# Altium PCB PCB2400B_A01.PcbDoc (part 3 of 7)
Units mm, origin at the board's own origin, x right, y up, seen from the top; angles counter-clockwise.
Board outline 115 x 60 mm, 6 copper layers (Top Layer, Signal Layer 2, Signal Layer 3, Signal Layer 4, Signal Layer 5, Bottom Layer), stack 1.555 mm thick; 382 components, 308 nets, 1384 pads, 1152 vias.
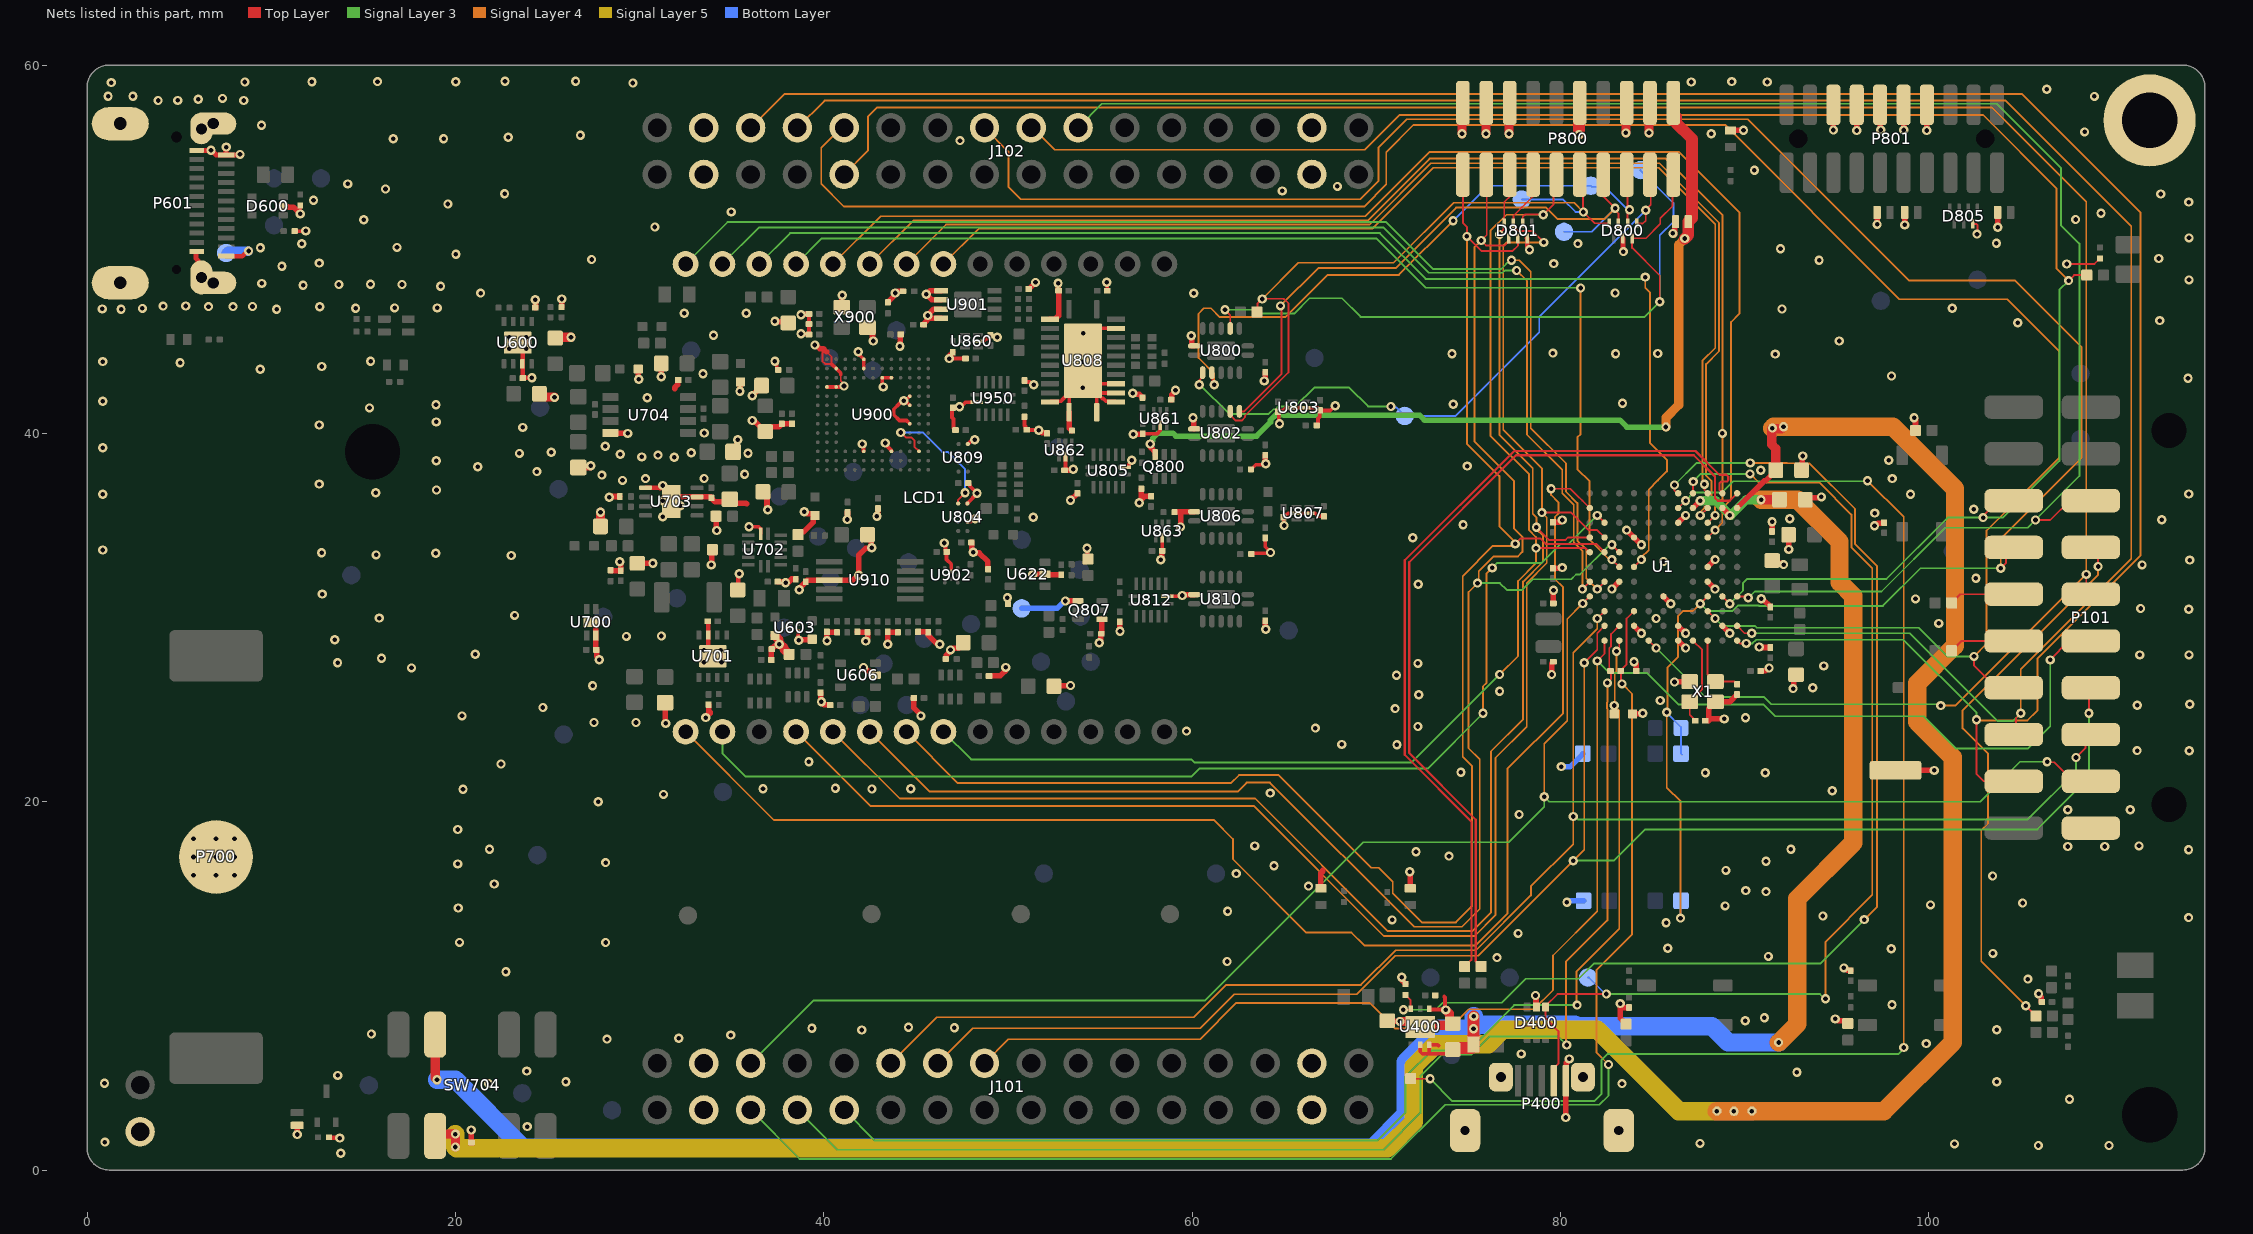
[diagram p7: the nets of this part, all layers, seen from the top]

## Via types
v1: diameter 0.5, hole 0.25, Top Layer to Bottom Layer, tented both sides, 773 vias
v2: diameter 0.508, hole 0.25, Top Layer to Bottom Layer, tented both sides, 379 vias

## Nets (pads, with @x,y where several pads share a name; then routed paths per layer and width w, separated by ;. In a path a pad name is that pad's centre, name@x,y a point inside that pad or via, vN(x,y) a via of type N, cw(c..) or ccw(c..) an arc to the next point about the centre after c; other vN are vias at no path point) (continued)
DEBUG_TMS_SWDIO_OUT: U804.D2 U900.C2 | length 7.8
  Top Layer w0.1: v2@44.275,39.975 44.275,39.972 44.472,39.775 44.779,39.775 44.925,39.629 44.925,39.275 U900.C2@45.175,39.025 ; U804.D2@47.3,36.2 47.3,36.4 v2(47.674,36.774)
  Bottom Layer w0.1: v2(44.177,40.052) 45.373,40.052 46.425,39 46.725,39 47.674,38.051 v2(47.674,36.774)
DEBUG_TRACECLK: D801.2 LCD1.8 P800.12 U1.E1 | length 68.9
  Top Layer w0.1: D801.2@77.95,51.415 77.955,51.42 77.955,51.771 78.084,51.9 79.1,51.9 79.621,52.421 79.621,53.813 P800.12@79.746,53.938 ; v1(78.675,33.775) 81.375,33.775 U1.E1@81.6,33.55
  Signal Layer 3 w0.1: LCD1.8@46.5,23.8 48,22.3 59.958,22.3 60.122,22.136 71.925,22.136 v1(76.7,26.911)
  Signal Layer 4 w0.1: v1(76.7,26.911) 77.7,27.911 77.7,31.983 78.675,32.958 v1(78.675,33.775) 78.675,34.375 78.3,34.75 78.3,37.775 76.2,39.875 76.2,51 77.075,51.875 v1(79.075,51.875)
DEBUG_TRACED0: D801.3 LCD1.4 P800.14 U1.D2 | length 92.7
  Top Layer w0.1: D801.3@77.45,51.415 77.45,51.807 78.515,52.872 P800.14@78.515,53.968 ; D801.3@77.475,51.22 77.695,51 78.475,51 v1(79.1,50.375) ; v1(79,35.7) 80.587,35.7 81.537,34.75 82,34.75 U1.D2@82.4,34.35
  Signal Layer 4 w0.1: LCD1.4@38.5,23.8 42.525,19.775 63.349,19.775 70.423,12.702 75.338,12.702 76.475,13.839 76.475,22.375 78.175,24.075 78.175,31.875 79.264,32.964 79.264,35.436 v1(79,35.7) 79,38.1 76.9,40.2 76.9,50.2 77.075,50.375 v1(79.1,50.375)
DEBUG_TRACED1: D801.4 LCD1.5 P800.16 U1.D1 | length 85.9
  Top Layer w0.1: v1@76.625,50.8 76.914,51.089 76.914,51.379 D801.4@76.95,51.415 76.95,52.567 77.325,52.942 P800.16@77.325,53.525 ; v1(78.7,34.9) 79.389,34.211 80.268,34.211 80.407,34.35 U1.D1@81.6,34.35
  Signal Layer 4 w0.1: LCD1.5@40.5,23.8 44.125,20.175 63.425,20.175 70.627,12.973 75.223,12.973 76.228,13.978 76.228,22.728 77.975,24.475 77.975,31.958 79.064,33.047 79.064,34.439 78.7,34.803 78.7,35.45 78.5,35.65 78.5,38.1 76.7,39.9 v1(76.7,50.8)
DEBUG_TRACED2: D801.5 LCD1.6 P800.18 U1.E3 | length 92.5
  Top Layer w0.1: P800.18@75.975,53.968 76,53.943 76,50.775 v1(75.7,50.475) 75.969,50.206 76.981,50.206 77.145,50.37 77.155,50.37 77.23,50.445 D801.5@77.23,50.455 ; v1(82.8,33.95) U1.E3@83.2,33.55
  Signal Layer 3 w0.1: v1(75.5,31.875) 76.715,31.875 77.09,31.5 77.925,31.5 78.503,32.078 80.589,32.078 80.85,32.339 81.064,32.339 82.675,33.95 v1(82.8,33.95)
  Signal Layer 4 w0.1: LCD1.6@42.5,23.8 45.75,20.55 62.475,20.55 62.964,21.039 64.227,21.039 72.057,13.209 74.659,13.209 75.625,14.175 75.625,22.295 75.011,22.909 75.011,31.386 v1(75.5,31.875) 75.569,31.944 75.569,32.519 76.375,33.325 77.7,33.325 77.939,33.564 77.939,34.378 77.489,34.828 77.489,37.411 75.336,39.564 75.336,50.111 v1(75.7,50.475)
DEBUG_TRACED3: D801.6 LCD1.7 P800.20 U1.E2 | length 87.8
  Top Layer w0.1: P800.20@74.705,53.968 74.705,51.445 74.925,51.225 v1(74.925,50.7) 75.725,49.9 77.4,49.9 77.7,50.2 D801.6@77.7,50.585 ; v1(77.55,34) 77.85,34.3 78.9,34.3 79.2,34 81.95,34 U1.E2@82.4,33.55
  Signal Layer 4 w0.1: LCD1.7@44.5,23.8 47.289,21.011 62.111,21.011 62.55,21.45 64.7,21.45 69.738,16.412 70.137,16.412 70.9,15.65 70.9,15.025 72.475,13.45 74.325,13.45 75.2,14.325 75.2,21.95 74.7,22.45 74.7,32.25 76.34,33.89 77.44,33.89 v1(77.55,34) 77.55,34.097 76.689,34.958 76.689,37.686 74.925,39.45 v1(74.925,50.7)
DH_#RESET: D800.4 P800.10 R816.1 TPJ811.1 U802.3 | length 37.9
  Top Layer w0.1: U802.3@62.075,41.2 62.075,41 62.375,40.7 62.699,40.7 62.875,40.876 62.875,40.95 65.239,43.314 65.239,47.061 65,47.3 64.975,47.3 64.962,47.313 63.82,47.313 v1(63.807,47.3) ; R816.1@63.525,46.6 63.55,46.625 63.55,47.05 v1@63.8,47.3 ; P800.10@81.016,53.988 81.222,53.782 81.222,52.053 v1(81.25,52.025) 81.86,51.415 D800.4@82.65,51.415
  Signal Layer 4 w0.1: v1(63.807,47.3) 65.773,49.266 70.941,49.266 74.2,52.525 80.75,52.525 v1(81.25,52.025)
  Bottom Layer w0.1: TPJ811.1@77.92,52.7 80.15,52.7 80.825,52.025 v1(81.25,52.025)
DH_TCK_SWCLK: D800.1 P800.4 TPJ818.1 U800.9 | length 35
  Top Layer w0.1: v2(60.4,42.65) 60.4,42.9 60.575,43.075 U800.9@60.575,43.3 ; D800.1@84.195,51.4 84.475,51.4 84.636,51.561 84.636,52.144 84.906,52.414 84.906,53.932 P800.4@84.87,53.968
  Signal Layer 3 w0.1: v2(60.4,42.65) 60.431,42.65 62.022,41.059 64.168,41.059 64.423,41.314 64.54,41.314 64.69,41.464 65.614,41.464 66.639,42.489 68.536,42.489 69.561,41.464 v1(70.8,41.464)
  Bottom Layer w0.1: v1(70.8,41.464) 70.854,41.41 71.09,41.41 TPJ818.1@71.55,40.95 72.45,40.95 74.313,40.95 78.858,45.495 78.858,46.341 v1(84.636,52.119)
DH_TDI: D800.3 P800.8 TPJ820.1 U802.2 | length 33.9
  Top Layer w0.1: U802.2@62.575,41.2 62.831,41.2 64.85,43.219 64.85,46.9 64.825,46.9 v1(64.801,46.924) ; P800.8@82.325,53.968 82.325,52.875 v1(82.975,52.225) 82.975,52.117 83.15,51.942 D800.3@83.15,51.415
  Signal Layer 4 w0.1: v1(64.801,46.924) 66.855,48.978 71.053,48.978 74.339,52.264 79.236,52.264 79.864,51.636 82.386,51.636 v1(82.975,52.225)
  Bottom Layer w0.1: TPJ820.1@80.2,50.95 81.7,50.95 v1(82.975,52.225)
DH_TDO_SWO: D800.2 P800.6 TPJ812.1 U800.10 | length 35
  Top Layer w0.1: v2@61.075,42.725 61.122,42.772 61.122,42.838 61.113,42.847 61.113,43.262 U800.10@61.075,43.3 ; P800.6@83.556,53.988 83.65,53.894 v1@83.65,52.15 ; D800.2@83.65,51.275 v1@83.65,52.15 ; v1(83.753,52.15) v1@83.65,52.15
  Signal Layer 4 w0.1: v2(61.2,42.65) 61.2,43.25 60.35,44.1 60.35,46.5 60.646,46.796 61.029,46.796 61.504,46.321 65.071,46.321 67.359,48.609 71.234,48.609 v1(74.175,51.55)
  Bottom Layer w0.1: v1@74.062,51.437 v1(74.175,51.55) 76.075,53.45 TPJ812.1@81.65,53.45 81.708,53.392 82.408,53.392 83.65,52.15 v1(83.753,52.15)
DH_TMS_SWDIO: D800.7 P800.2 TPJ814.1 U800.3 | length 42.9
  Top Layer w0.1: v2(61.789,46.714) 62.075,46.427 U800.3@62.075,45.7 ; v1(85.4,47.15) 85.4,48.575 83.9,50.075 83.9,50.555 83.945,50.6 84.65,50.6 85.425,51.375 85.425,51.68 86.096,52.351 P800.2@86.096,53.988
  Signal Layer 3 w0.1: v2(61.789,46.714) 63.625,46.714 63.827,46.511 65.553,46.511 66.379,47.337 68.142,47.337 69.152,46.327 84.577,46.327 v1(85.4,47.15)
  Bottom Layer w0.1: TPJ814.1@84.35,54.3 86.144,52.506 86.144,51.495 85.4,50.751 v1(85.4,47.15)
DH_VTREF: D809.1 P800.1 Q800.3 | length 47.7
  Top Layer w0.3: v2(57.725,39.425) 57.765,39.385 57.765,39.235 58,39 Q800.3@58,38.85
  Top Layer w0.635: P800.1@86.275,57.2 86.275,56.868 87.15,55.993 87.15,51.7 D809.1@86.983,51.533 ; v1(86.761,50.583) 86.95,50.772 D809.1@86.95,51.5
  Signal Layer 3 w0.3: v2(57.725,39.425) 57.725,39.481 57.857,39.613 57.857,39.729 58.146,40.018 58.96,40.018 59.121,39.857 63.507,39.857 64.261,40.611 64.261,40.728 64.547,41.014 64.953,41.014 64.991,40.975 72.373,40.975 72.623,40.725 83.238,40.725 83.616,40.347 v1(85.734,40.347)
  Signal Layer 4 w0.5: v1(85.734,40.347) 85.734,40.859 86.425,41.55 86.425,50.247 v1(86.761,50.583)
EFM_USB_DM: R406.2 U1.A10 | length 45.7
  Top Layer w0.12: R406.2@74.8,11.05 75.168,11.418 75.168,18.927 71.55,22.545 71.55,33.108 77.493,39.051 87.343,39.051 88.636,37.758 89.007,37.758 89.118,37.647 89.118,37.465 89.048,37.395 88.75,37.395 88.636,37.281 88.636,36.935 88.8,36.771 U1.A10@88.8,36.75
EFM_USB_DP: R405.2 U1.A11 | length 45.7
  Top Layer w0.12: R405.2@75.7,11.05 75.408,11.342 75.408,19.026 71.79,22.644 71.79,33.009 77.592,38.811 87.243,38.811 88.394,37.661 88.394,36.499 88.545,36.348 89.198,36.348 U1.A11@89.6,36.75
EFM_USB_ID: D400.1 P400.4 TPJ402.1 U1.A8 | length 59.5
  Top Layer w0.1: P400.4@79.65,4.85 79.65,5.525 79.897,5.771 79.897,7.548 79.2,8.245 79.2,8.912 79.847,9.56 v1(82.503,9.56) ; U1.A8@87.2,36.75 87.213,36.763 v1(87.213,37.386)
  Signal Layer 3 w0.1: v1(82.503,9.56) 94.094,9.56 v1@94.354,9.3 ; v1(87.213,37.386) 87.627,37.8 v1(90.3,37.8)
  Signal Layer 4 w0.1: v1(90.3,37.8) 90.759,37.341 94.059,37.341 95.807,35.593 95.807,33.82 96.939,32.688 96.939,14.939 94.4,12.4 v1(94.4,9.3)
  Bottom Layer w0.1: TPJ402.1@81.5,10.45 81.556,10.45 82.447,9.56 v1(82.503,9.56)
EFM_USB_OC_FAULT: R408.1 U1.B7 | length 72.1
  Top Layer w0.1: U1.B7@86.401,35.95 v1(86.801,36.35)
  Top Layer w0.102: R408.1@71.874,4.968 71.883,4.959 v1(72.927,4.959)
  Signal Layer 3 w0.102: v1(72.927,4.959) 74.141,3.745 81.842,3.745 82.226,4.128 82.226,5.966 82.56,6.3 98.36,6.3 98.647,6.587 v1(98.647,6.654) ; v1(86.801,36.35) 87.251,36.8 88.8,36.8 89.4,37.4 96.645,37.4 v1(96.677,37.432)
  Signal Layer 4 w0.102: v1(96.677,37.432) 98.647,35.463 v1(98.647,6.654)
EFM_USB_VBUS: C402.1 C420.1 L401.2 SW704.6 U1.B8 U1.B10 U400.5 U400.6 | length 128.4
  Top Layer w0.2: U400.5@72.387,6.801 72.387,6.426 72.504,6.309 72.765,6.309 ; 73.382,6.757 73.338,6.801 U400.6@72.887,6.801 72.882,6.796 72.882,6.426 72.765,6.309 ; C420.1@74.151,6.545 73.915,6.309 72.765,6.309
  Top Layer w0.3: U1.B8@87.201,35.95 v1(87.601,36.35) ; U1.B10@88.8,35.95 v1(89.201,35.55)
  Top Layer w0.5: SW704.6@18.9,7.25 18.9,5 v1(19,4.9) ; v1(90.9,36.4) C402.1@91.8,36.4
  Top Layer w0.635: C420.1@74.151,6.545 C420.1@74.176,6.545 ; C420.1@74.233,6.628 L401.2@75.198,6.628 ; L401.2@75.286,6.716 75.286,7.666 v1(75.283,7.669) 75.283,8.33 v1(75.297,8.344)
  Signal Layer 3 w0.5: v1(87.601,36.35) 88.439,36.35 89.201,35.588 v1(89.201,35.55) 89.25,35.55 90.1,36.4 v1(90.9,36.4)
  Signal Layer 4 w1: v1(90.9,36.4) 92.885,36.4 95.157,34.128 95.157,31.927 95.904,31.18 95.904,17.775 92.871,14.742 92.871,7.93 91.868,6.927 v1(91.853,6.927)
  Bottom Layer w1: v1(19,4.9) 20,4.9 23.7,1.2 69.8,1.2 71.6,3 71.6,5.864 73.405,7.669 v1(75.283,7.669) 75.283,8.33 v1(75.297,8.344) ; 75.5,7.886 80.794,7.886 80.868,7.812 88.234,7.812 89.118,6.927 v1(91.853,6.927)
EFM_USB_VBUSEN: R407.2 U1.A7 U400.3 | length 63.4
  Top Layer w0.1: v1(71.478,8.703) 71.839,8.703 U400.3@71.887,8.751 71.871,8.767 71.871,9.226 71.714,9.383 71.704,9.383 71.594,9.493 R407.2@71.594,9.503 ; v1(86.2,37.2) 86.2,36.884 86.334,36.75 U1.A7@86.4,36.75 U1.A7@86.425,36.75 ; v1@86.2,37.225 v1@86.212,37.213
  Signal Layer 3 w0.1: v1(71.478,8.703) 71.481,8.7 73.238,8.7 ; 73.24,8.702 73.622,9.085 76.808,9.085 78.109,10.386 80.986,10.386 81.813,11.213 ; 81.811,11.211 94.111,11.211 v1(96.5,13.6) ; v1(86.2,37.2) 87.4,38.4 v1(90.315,38.4)
  Signal Layer 4 w0.1: v1(90.315,38.4) 90.321,38.394 92.302,38.394 92.311,38.385 93.519,38.385 96.007,35.897 96.007,33.98 97.2,32.787 97.2,14.3 v1(96.5,13.6)
EFM_USB_VREGO: C401.1 SW704.2 U1.B11 | length 142.7
  Top Layer w0.3: U1.B11@89.6,35.95 91.071,37.422 91.146,37.422 91.7,37.975 C401.1@91.7,38
  Top Layer w0.5: SW704.2@18.9,1.95 v1(20,1.95) v1(20,1.25) ; v1(91.516,40.288) v1@91.478,40.249 ; C401.1@91.7,38 91.7,39.175 91.478,39.397 v1@91.478,40.249 ; v1(92.115,40.364) 92,40.249 v1@91.478,40.249
  Signal Layer 4 w1: v1(88.5,3.2) 88.505,3.195 v1(89.424,3.195) 89.428,3.2 v1(90.4,3.2) 97.574,3.2 101.304,6.93 101.304,22.41 99.378,24.336 99.378,26.424 101.43,28.476 101.43,36.999 98.064,40.365 v1(92.115,40.364) ; v1(91.516,40.288) 91.593,40.364 v1(92.115,40.364)
  Signal Layer 5 w1: v1(20,1.95) 20,1.842 v1(20,1.25) 20.068,1.182 70.598,1.182 72.029,2.614 72.029,5.627 73.233,6.83 76.089,6.83 76.887,7.628 82.003,7.628 86.431,3.2 v1(88.5,3.2) 88.505,3.195 v1(89.424,3.195) 90.395,3.195 v1(90.4,3.2)
EXP_HEADER3: J101.6 P101.3 U1.H1 | length 92.2
  Top Layer w0.1: v1(81.216,30.765) U1.H1@81.6,31.15 ; v1(106.43,22.17) 106.459,22.141 106.83,22.141 107.86,21.11 P101.3@108.557,21.11
  Signal Layer 3 w0.1: J101.6@36.03,5.802 39.428,9.2 60.7,9.2 69.3,17.8 77.2,17.8 79.13,19.73 v1(79.13,20.27) 79.4,20 102.791,20 104.961,22.17 v1(106.43,22.17)
  Signal Layer 4 w0.1: v1(79.13,20.27) 79.13,23.155 80.375,24.4 80.375,29.924 81.2,30.749 v1(81.216,30.765)
EXP_HEADER4: J102.6 P101.4 U1.L11 | length 132.2
  Top Layer w0.1: U1.L11@89.6,28.75 U1.L11@89.602,28.75 ; U1.L11@89.6,28.752 U1.L11@89.602,28.75 ; v1(90.1,28.6) 89.752,28.6 U1.L11@89.602,28.75 ; v1(102.6,24.45) 102.6,21.5 102.99,21.11 P101.4@104.623,21.11 P101.4@104.747,21.11
  Signal Layer 3 w0.1: v1(90.1,28.6) 90.433,28.6 90.633,28.8 98.625,28.8 102.6,24.825 v1(102.6,24.45)
  Signal Layer 4 w0.1: J102.6@36.03,56.602 37.856,58.428 105.084,58.428 111.5,52.012 111.5,33.367 105.903,27.77 105.903,24.948 105.366,24.411 102.639,24.411 v1(102.6,24.45)
EXP_HEADER5: J101.12 P101.5 U1.J2 | length 93.7
  Top Layer w0.1: v1(82,29.949) U1.J2@82.4,30.35 ; v1@108.025,22.425 108.524,22.924 108.524,23.616 P101.5@108.557,23.65
  Signal Layer 3 w0.1: J101.12@43.65,5.802 J101.12@44.064,5.802 ; v1(80.7,19.2) 80.803,19.2 80.959,19.044 105.381,19.044 108,21.663 v1(108,22.4)
  Signal Layer 4 w0.1: J101.12@43.65,5.802 46.148,8.3 60.1,8.3 61.85,10.05 ; 68.9,10.05 61.85,10.05 ; v1(82,29.949) 82,29.4 80.7,28.1 v1(80.7,19.2) 80.7,17.7 78.4,15.4 78.4,14.916 75.42,11.936 71.059,11.936 69.173,10.05 61.85,10.05
EXP_HEADER6: J102.8 P101.6 U1.K11 | length 123.8
  Top Layer w0.1: U1.K11@89.6,29.55 90.001,29.149 v1(90.399,29.149) ; P101.6@104.747,23.65 104.747,24.547 v1(105,24.8)
  Signal Layer 3 w0.1: v1(90.399,29.149) 98.976,29.149 103.75,24.375 104.575,24.375 v1(105,24.8)
  Signal Layer 4 w0.1: J102.8@38.57,56.602 40.045,58.077 104.175,58.077 111,51.252 111,33.192 105,27.192 v1(105,24.8)
EXP_HEADER7: J101.14 P101.7 U1.K2 | length 87.3
  Top Layer w0.1: v1(81.299,27.549) 82,28.25 82,29.15 U1.K2@82.4,29.55 ; P101.7@108.557,26.19 108.7,26.047 v1(108.7,24.8)
  Signal Layer 3 w0.1: v1(80.7,16.8) 82.9,16.8 84.6,18.5 105.908,18.5 108.7,21.292 v1(108.7,24.8)
  Signal Layer 4 w0.1: J101.14@46.19,5.802 48.088,7.7 60.45,7.7 62.3,9.55 68.956,9.55 71.044,11.638 75.538,11.638 v1(80.7,16.8) 81.299,17.399 v1(81.299,27.549)
EXP_HEADER8: J102.10 P101.8 U1.J9 | length 116.6
  Top Layer w0.1: U1.J9@88,30.35 v1(88.401,29.949) ; v1(102.465,27.891) 102.465,27.391 103.666,26.19 P101.8@104.747,26.19
  Signal Layer 3 w0.1: v1(88.401,29.949) 88.807,29.543 90.579,29.542 90.677,29.444 99.456,29.444 101.009,27.891 v1(102.465,27.891)
  Signal Layer 4 w0.1: J102.10@41.11,56.602 40.942,56.602 39.861,55.521 39.861,53.559 41.099,52.321 69.343,52.321 70.543,53.521 70.543,55.27 72.026,56.753 88.948,56.753 98.415,47.286 104.265,47.286 107.089,44.462 107.089,38.671 103.142,34.724 103.142,28.568 v1(102.465,27.891)
EXP_HEADER9: J101.16 P101.9 U1.L2 | length 86.9
  Top Layer w0.1: v1(82,27.65) v1(82,27.65) 82.399,28.049 U1.L2@82.399,28.752 ; v1@106.575,27.625 106.575,27.688 107.617,28.73 P101.9@108.557,28.73
  Signal Layer 3 w0.1: v1(82,27.65) 82.65,27 84.7,27 86.427,25.272 91.039,25.272 91.67,24.642 99.729,24.642 101.471,22.9 105.4,22.9 106.6,24.1 v1(106.6,27.7)
  Signal Layer 4 w0.1: J101.16@48.73,5.802 50.028,7.1 60.436,7.1 62.411,9.075 69.65,9.075 71.041,7.684 73.988,7.684 75.037,8.733 78.56,8.733 79.6,9.773 79.6,11.651 82,14.052 v1(82,27.65)
EXP_HEADER10: P101.10 R241.2 | length 3.7
  Top Layer w0.127: R241.2@101.25,28.2 101.78,28.73 P101.10@104.747,28.73
EXP_HEADER11: J102.9 P101.11 U1.L5 | length 121.6
  Top Layer w0.1: U1.L5@84.8,28.75 v1(85.2,28.349) ; P101.11@108.557,31.27 v1(108.557,32.343)
  Signal Layer 3 w0.1: v1(85.2,28.349) 87.856,25.693 91.055,25.693 91.45,25.298 100.582,25.298 v1(100.658,25.221)
  Signal Layer 4 w0.1: J102.9@41.11,54.062 42.4,55.352 42.4,57.2 42.901,57.701 103.435,57.701 108.557,52.579 v1(108.557,32.343) 101.436,25.221 v1(100.658,25.221)
EXP_HEADER12: P101.12 R242.2 | length 3.7
  Top Layer w0.102: R242.2@101.25,30.8 101.72,31.27 P101.12@104.747,31.27
EXP_HEADER13: P101.13 R300.2 | length 31.1
  Top Layer w0.1: v1(105.275,8.925) R300.2@105.825,8.375 ; P101.13@108.557,33.81 109.2,33.81 v1(109.2,32.775)
  Signal Layer 4 w0.1: v1(105.275,8.925) 102.854,11.347 102.854,18.443 103.229,18.819 103.229,22.6 101.847,23.983 101.847,24.972 109.2,32.325 v1(109.2,32.775)
EXP_HEADER14: C250.2 J102.16 P101.14 R243.2 R245.2 U1.H9 | length 125.7
  Top Layer w0.1: v1(87.601,30.749) 88,31.148 U1.H9@88,31.15 ; v1(103.914,32.679) 104.197,32.962 104.197,33.26 P101.14@104.747,33.81
  Signal Layer 3 w0.1: v1(87.601,30.749) 87.99,30.36 89.362,30.36 89.667,30.665 90.762,30.665 90.791,30.636 97.515,30.636 99.558,32.679 v1(103.914,32.679)
  Signal Layer 4 w0.1: J102.16@48.73,56.602 50.031,55.301 50.031,53.388 50.699,52.72 69.136,52.72 70.121,53.705 70.121,55.516 71.665,57.06 90.171,57.06 98.919,48.312 104.67,48.312 108.307,44.675 108.307,38.683 104.017,34.393 103.914,34.29 v1(103.914,32.679) ; v1(86.526,13.68) 86.526,20.025 85.781,20.77 v1(85.781,24.858) 85.811,24.888 85.811,27.284 86.391,27.864 86.391,30.089 86.662,30.36 87.212,30.36 v1(87.601,30.749)
  Bottom Layer w0.1: v1(85.781,24.858) 85.781,24.825 86.551,24.055 R245.2@86.551,22.617 R245.2@86.617,22.551 ; v1(86.526,13.68) 86.526,14.6 R243.2@86.551,14.625
EXP_HEADER15: J102.20 P101.15 U1.H11 | length 97
  Top Layer w0.1: U1.H11@89.6,31.15 90.131,31.15 v1(90.204,31.077) ; v1(105.8,35.3) 106.6,35.3 107.65,36.35 P101.15@108.557,36.35
  Signal Layer 3 w0.1: J102.20@53.81,56.602 55.108,57.9 103.7,57.9 107.183,54.416 107.183,51.316 108.189,50.311 108.189,37.689 v1(105.8,35.3) 105.378,34.878 100.902,34.878 97.439,31.415 90.565,31.415 90.226,31.077 v1(90.204,31.077)
EXP_HEADER16: J102.18 P101.16 R307.1 U1.H10 | length 99.2
  Top Layer w0.1: U1.H10@88.8,31.15 v1(89.201,30.749) ; v1(102.957,35.43) 102.957,35.533 103.774,36.35 P101.16@104.747,36.35 ; v1(107.6,48.3) 107.9,48.6 R307.1@108.65,48.6
  Signal Layer 3 w0.1: v1(89.201,30.749) 89.917,31.465 89.911,31.472 89.911,31.861 90.15,32.1 97.71,32.1 101.04,35.43 v1(102.957,35.43) ; v1@103.124,35.43 104.019,35.43 107.1,38.511 107.1,47.8 v1(107.6,48.3)
  Signal Layer 4 w0.1: J102.18@51.27,56.602 51.344,56.602 52.542,55.404 69.39,55.404 71.28,57.294 102.951,57.294 106.95,53.295 106.95,48.95 v1(107.6,48.3) ; J102.18@51.35,56.825 J102.18@51.493,56.825
GND: C3.2 C4.2 C5.2 C6.2 C8.2 C9.2 C10.2 C13.2 C14.2 C15.2 C16.2 C40.2 C102.2 C103.2 C199.2 C200.2 C401.2 C402.2 C417.2 C418.2 C419.2 C420.2 C421.2 C422.2 C423.2 C600.2 C602.2 C607.2 C608.2 C609.2 C610.2 C611.2 C621.2 C625.2 C632.2 C635.2 C638.2 C641.2 C652.2 C653.2 C655.2 C660.2 C673.2 C674.2 C700.2 C701.2 C702.2 C703.2 C705.2 C706.2 C707.2 C708.2 C714.2 C720.2 C724.2 C728.2 C729.2 C730.2 C731.2 C800.2 C803.2 C804.2 C805.2 C806.2 C807.2 C808.2 C809.2 C810.2 C827.2 C828.2 C860.2 C861.2 C862.2 C863.2 C864.2 C865.2 C866.2 C867.2 C868.2 C869.2 C870.2 C900.2 C901.2 C902.2 C903.2 C904.2 C905.2 C906.2 C907.2 C908.2 C909.2 C910.2 C911.2 C914.2 C921.2 C922.2 C924.2 C925.2 C926.2 C927.2 C950.2 C951.2 D400.2 D600.2 D703.2 D800.6 D801.7 D805.7 D806.2 D807.2 D808.2 D809.2 J101.3 J101.4 J101.29 J101.30 J102.3 J102.4 J102.29 J102.30 LED100.2 LED101.2 LED900.2 M1.1 P101.1 P400.5 P400.6 P400.7 P400.8 P400.9 P601.25@1.8,56.82 P601.26@1.8,48.18 P601.27@6.2,56.525 P601.27@6.85,56.82 P601.28@6.2,48.475 P601.28@6.85,48.18 P601.A1 P601.A12 P601.B1 P601.B12 P700.2 P800.3 P800.5 P800.9 P800.15 P800.17 P800.19 P801.7 P801.9 P801.11 P801.13 P801.15 Q807.1 Q807.4 R7.1 R104.2 R105.2 R199.2 R240.1 R244.1 R407.1 R602.1 R620.1 R621.1 R623.1 R628.2 R631.1 R634.1 R637.1 R640.1 R674.2 R688.2 R691.2 R703.1 R705.1 R706.1 R707.1 R708.1 R718.1 R760.1 R763.1 R767.1 R771.1 R792.1 R807.2 R808.2 R814.1 R817.1 R839.1 R850.1 R851.1 R852.1 R853.1 R930.2 R931.2 R950.2 R981.2 ST701.1 TPJ614.1 TPJ913.1 U1.C7 U1.D4 U1.F9 U1.G3 U1.G9 U1.H6 U1.K4 U1.K7 U1.K10 U1.L7 U400.1 U400.7 U600.3 U600.9 U603.A1 U606.2 U622.2 U700.2 U700.5 U701.3 U701.9 U702.7 U703.3 U703.5 U703.9 U704.4 U800.7 U802.7 U803.2 U803.5 U804.B1 U804.D1 U805.7 U806.7 U807.2 U807.5 U808.2 U808.11 U808.12 U808.13 U808.14 U808.15 U808.16 U808.22 U808.25 U809.D1 U810.7 U812.7 U860.2 U861.2 U862.2 U863.2 U900.C5 U900.C8 U900.F3 U900.H3 U900.J3 U900.K11 U900.K12 U900.L5 U900.L6 U900.M8 U900.M11 U900.N8 U901.1 U901.2 U901.3 U901.4 U902.B2 U910.3 U950.7 X1.2 X1.4 X900.2 X900.4 | length 224.7
  Top Layer w0.1: 39.925,44.525 39.925,43.921 40.071,43.775 40.279,43.775 40.425,43.775 ; 40.15,44.425 40.425,44.15 40.425,43.921 ; C638.2@40.175,29.225 C638.2@40.188,29.212 ; R637.1@40.712,29.212 40.718,29.218 R637.1@40.725,29.225 ; 40.925,43.199 40.925,42.861 41.099,42.687 v2(41.099,42.577) ; v1(81.011,56.22) 81.011,56.27 v1@81.016,56.275 ; D805.7@102.4,51.385 102.435,51.385 102.445,51.375 102.595,51.375 102.654,51.316 102.654,50.854 v1(102.625,50.825) ; 40.425,43.775 40.425,43.921 ; 40.425,43.775 40.425,43.921
  Top Layer w0.102: C423.2@70.605,8.102 70.62,8.087 70.634,8.073 v1(71.289,8.073) ; v1(107.5,49.2) 109,49.2 R199.2@109.3,49.5
  Top Layer w0.2: R621.1@11.27,50.987 11.862,50.987 v1(11.875,51) ; v1(11.568,51.92) 11.571,51.924 11.571,52.371 R620.1@11.575,52.375 ; v2(35.94,34.929) 35.943,34.932 36.458,34.932 36.575,34.815 U702.7@36.575,34.56 ; C900.2@36.625,42.6 C900.2@36.675,42.6 ; v2(37.35,43.925) 37.35,43.842 37.455,43.737 37.455,43.51 37.515,43.45 R763.1@37.525,43.45 ; U603.A1@38.625,29.25 38.619,29.244 38.619,29.026 38.6,29.007 38.6,28.777 v2(38.635,28.777) ; v2(38.763,45.414) 38.786,45.391 39.177,45.391 C904.2@39.199,45.369 C905.2@39.199,45.945 C906.2@39.199,46.494 ; U900.K12@40.175,42.525 U900.K11@40.675,42.525 41.047,42.525 v2(41.099,42.577) ; 40.425,43.775 U900.M11@40.675,43.525 40.925,43.275 40.925,43.199 ; v2(41.881,44.43) 41.85,44.461 41.803,44.461 41.803,44.397 U900.N8@42.175,44.025 U900.M8@42.175,43.525 ; v2(42.1,39.425) 42.159,39.366 42.159,39.041 U900.C8@42.175,39.025 ; v2(43.225,42.525) 43.175,42.575 U900.L6@43.175,43.025 U900.L5@43.675,43.025 ; v2(43.347,39.479) 43.347,39.396 43.675,39.068 U900.C5@43.675,39.025 ; v2@44.45,41.8 U900.J3@44.675,42.025 ; U900.F3@44.675,40.525 44.493,40.707 44.117,40.707 43.803,41.02 43.803,41.316 44.114,41.627 44.119,41.627 44.267,41.775 44.425,41.775 U900.H3@44.675,41.525 ; v2(46.55,34.05) 46.609,33.991 46.609,33.625 C914.2@46.669,33.565 ; C914.2@46.678,33.565 C914.2@46.669,33.565 ; v2@46.808,44.065 C863.2@47.695,44.064 ; U902.B2@46.925,32.5 46.923,32.502 46.923,32.905 46.669,33.159 C914.2@46.669,33.565 ; C911.2@46.968,41.375 46.968,40.868 47.043,40.793 47.043,40.288 47.075,40.256 47.075,40.236 47.135,40.176 C909.2@47.155,40.176 ; C911.2@47.011,41.385 47.043,41.417 47.342,41.417 v2(47.375,41.45) 47.458,41.45 47.708,41.7 U950.7@48.315,41.7 ; U804.B1@47.8,35.2 47.806,35.206 47.972,35.206 48.142,35.375 v2(48.225,35.375) ; U804.D1@47.8,36.2 47.8,36.208 48.325,36.733 v2(48.325,36.75) 47.93,37.145 47.93,37.24 47.87,37.3 C810.2@47.85,37.3 ; U809.D1@47.825,39.425 47.833,39.425 47.999,39.591 48.141,39.591 v2(48.2,39.65) ; U860.2@48.374,45.009 48.685,45.009 48.831,45.155 48.9,45.155 49.05,45.305 C862.2@49.05,45.325 49.1,45.275 49.363,45.275 v2(49.413,45.225) ; R950.2@50.9,40.9 50.9,40.43 50.955,40.375 50.955,40.26 51.015,40.2 R981.2@51.025,40.2 51.038,40.187 51.662,40.187 v2(51.675,40.175) ; C950.2@50.9,42.875 50.9,42.855 50.96,42.795 51.172,42.795 51.317,42.65 v2(51.4,42.65) ; U808.11@52.28,41.7 52.32,41.74 52.865,41.74 52.994,41.869 U808.25@53.325,42.2 ; C860.2@53.075,38 53.125,38.05 U862.2@53.125,38.75 ; U808.12@53.325,41.155 U808.25@53.325,42.2 ; v2(54.1,45.45) 54.365,45.715 55.855,45.715 U808.22@55.87,45.7 ; v1(54.297,33.768) 54.324,33.741 54.324,33.21 R691.2@54.351,33.183 ; U808.13@54.825,41.155 U808.25@54.825,42.2 ; v2(55.375,48.2) 55.387,48.188 55.387,47.763 C806.2@55.4,47.75 ; U808.14@55.87,41.7 55.83,41.74 55.335,41.74 55.181,41.894 55.131,41.894 54.875,42.15 U808.25@54.875,42.2 ; U808.15@55.87,42.2 U808.25@54.875,42.2 ; U808.16@55.87,42.7 54.3,42.7 v2(54.075,42.475) ; U805.7@56.335,38.17 56.575,38.17 56.575,38.324 56.718,38.467 v2(56.718,38.55) ; C864.2@57.325,39.975 58.096,39.975 58.275,40.154 U861.2@58.275,40.45 ; C866.2@58.375,33.625 58.375,34.175 U863.2@58.375,34.35 ; U812.7@58.66,31.15 59.425,31.15 v2(59.475,31.2) ; R807.2@63.2,38.05 63.21,38.05 63.455,38.295 63.934,38.295 v2(63.993,38.354) ; R808.2@63.219,33.444 63.264,33.489 64.214,33.489 v1(64.259,33.534) 64.259,33.561 63.975,33.845 C809.2@63.975,34.325 ; v1(64.75,40.525) 64.706,40.569 64.706,41.127 C869.2@64.663,41.17 64.663,41.19 64.723,41.25 64.95,41.25 65.1,41.4 U803.2@65.45,41.4 U803.5@66.15,41.4 66.82,41.4 66.95,41.27 C807.2@66.95,41.25 ; v1(64.998,35.001) 64.981,35.018 64.981,35.428 C870.2@64.964,35.445 64.964,35.465 65.114,35.615 65.184,35.615 65.228,35.66 U807.2@65.68,35.66 U807.5@66.38,35.66 66.689,35.66 66.837,35.511 67.146,35.511 C868.2@67.162,35.495 ; R817.1@66.77,40.436 66.78,40.436 66.84,40.496 66.84,40.815 66.942,40.917 66.942,41.242 C807.2@66.95,41.25 ; v1(67.775,41.5) 67.758,41.5 67.508,41.25 C807.2@66.95,41.25 ; U400.1@72.887,8.751 72.887,8.748 72.912,8.722 v1@73.753,8.722 ; 73.688,9.423 73.735,9.376 73.735,8.741 v1@73.753,8.722 ; v1(73.782,8.694) v1@73.753,8.722 ; U808.25@53.325,42.2 53.6,42.475 v2(54.075,42.475) ; v2(54.075,42.475) 54.6,42.475 U808.25@54.875,42.2
  Top Layer w0.25: U703.5@30.325,37.05 v2@31.125,37.05 ; C702.2@33.7,29.8 33.725,29.775 U701.3@33.725,29.05 33.725,28.15 U701.9@33.975,27.9 ; C703.2@35.325,31.5 35.361,31.536 35.361,32.326 35.396,32.361 35.396,32.371 v2(35.403,32.378) ; R623.1@37.175,28.35 37.21,28.385 37.22,28.385 37.336,28.501 37.406,28.501 37.526,28.501 37.535,28.51 v2(37.575,28.55)
  Top Layer w0.254: P601.B1@5.95,49.875 5.921,49.875 5.913,49.867 5.913,49.5 6.019,49.394 6.019,48.656 P601.28@6.2,48.475 ; P601.A12@7.55,49.625 8.419,49.625 8.699,49.905 v1(8.766,49.905) ; R792.1@13.144,1.782 13.166,1.76 13.693,1.76 v1(13.716,1.737) ; U600.9@23.375,44.95 23.65,44.675 23.65,43.767 U600.3@23.637,43.78 ; U600.3@23.65,43.75 23.65,43.017 C600.2@23.662,43.005 23.671,43.015 24.14,43.015 v1(24.15,43.025) ; D801.7@78.193,50.592 D801.7@78.2,50.585 78.2,50.167 78.325,50.042 v1(78.325,49.975) ; D800.6@83.4,50.585 83.4,49.9 v1(83.425,49.875)
  Top Layer w0.27: P601.B12@5.95,55.375 v1(6.725,55.375) ; v1@6.787,55.337 6.998,55.125 P601.A1@7.55,55.125 ; v1(7.55,55.55) P601.A1@7.55,55.125 ; v1(8.3,55.15) 8.275,55.125 P601.A1@7.55,55.125
  Top Layer w0.3: D600.2@10.65,52.35 10.687,52.312 10.885,52.312 10.91,52.287 11.198,52.287 11.565,51.92 v1(11.568,51.92) ; D703.2@11.403,2.423 11.407,2.419 11.407,1.932 v1(11.411,1.928) ; v1(24.334,47.26) 24.357,47.237 24.357,46.83 C602.2@24.337,46.83 ; R602.1@25.762,46.855 25.762,47.287 v1(25.775,47.3) ; R767.1@26.675,38.15 26.688,38.138 27.356,38.138 v2(27.356,38.242) ; U700.5@27.375,29.75 27.525,29.75 27.625,29.65 U700.2@27.625,29.025 27.625,28.26 27.635,28.25 C708.2@27.65,28.25 27.67,28.25 27.68,28.24 27.68,27.888 27.81,27.758 v2(27.81,27.702) ; v2(28.35,36.543) v2@28.35,36.575 ; v2@28.35,36.575 C728.2@28.925,36.575 ; U704.4@28.42,40.025 28.432,40.012 29.338,40.012 v2(29.35,40) ; R760.1@28.425,32.575 28.425,32.565 28.435,32.555 28.475,32.555 28.48,32.55 C701.2@28.975,32.55 28.985,32.56 28.985,32.909 28.925,32.969 v2(28.925,33.025) ; C700.2@29.875,32.95 v2(30.725,32.95) ; C720.2@29.925,43.5 29.938,43.488 29.938,42.962 v2(29.95,42.95) ; v2@31.125,37.05 v2(31.25,37.175) ; v2(31.175,43.075) C731.2@31.175,43.8 ; R703.1@31.383,25.373 31.401,25.355 31.401,24.273 v1(31.419,24.255) ; 31.9,42.425 31.9,42.481 32.07,42.651 32.07,42.89 32.08,42.9 C730.2@32.1,42.9 ; v2(32.2,36.075) 31.95,36.075 U703.9@31.725,36.3 31.975,36.55 U703.3@33.125,36.55 33.87,36.55 33.9,36.52 C729.2@33.9,36.5 33.9,36.48 34.099,36.281 R718.1@34.893,36.281 ; v1(33.597,24.57) 33.597,24.624 33.75,24.777 C705.2@33.75,25.275 33.76,25.265 33.76,24.931 33.83,24.861 33.83,24.805 ; v1(33.894,32.859) v1@33.924,32.889 ; v1@33.927,32.892 v1@33.924,32.889 ; R705.1@33.953,33.685 33.924,33.655 v1@33.924,32.889 ; v1@34.153,34.769 v1@34.172,34.75 ; R706.1@34.153,35.503 34.172,35.484 v1@34.172,34.75 ; v1@34.245,34.731 v1(34.191,34.731) v1@34.172,34.75 ; R718.1@34.893,36.425 35.107,36.211 35.771,36.211 35.811,36.171 ; R771.1@35.075,39 35.285,39.21 35.285,39.61 v2(35.325,39.65) ; v2(35.45,42.3) 35.462,42.312 35.462,42.788 C724.2@35.475,42.8 ; v2(36.122,42.052) 36.122,42.072 36.6,42.55 C900.2@36.625,42.55 ; v2(36.125,40.703) 36.125,40.65 36.165,40.61 36.29,40.61 36.825,40.075 37.1,40.35 37.57,40.35 37.725,40.505 C924.2@37.725,40.525 C925.2@38.275,40.525 ; C902.2@36.7,36.825 36.919,36.606 36.919,35.894 v2(36.959,35.854) ; C610.2@37.157,27.702 R623.1@37.157,28.322 ; R623.1@37.182,28.287 37.192,28.287 37.406,28.501 37.415,28.51 v2@37.535,28.51 ; v2(37.35,46.1) 37.39,46.06 38.015,46.06 C903.2@38.075,46 ; C707.2@37.5,31.95 37.51,31.94 37.813,31.94 37.878,31.875 v2@37.927,31.875 ; v2(37.927,31.883) v2@37.927,31.875 ; v2@37.935,31.875 v2@37.927,31.875 ; v2@37.975,31.858 38.031,31.914 38.074,31.914 38.27,32.11 38.28,32.099 38.473,32.099 38.483,32.089 R708.1@38.483,32.079 ; R707.1@38.6,34.502 38.75,34.652 38.911,34.652 39.425,35.166 C901.2@39.425,35.65 ; v2(38.635,28.777) 38.635,28.8 C608.2@39.35,28.8 ; v2(38.664,31.508) 38.664,31.565 39.1,32.001 39.1,32.025 U910.3@40.3,32.025 41.574,32.025 41.843,32.294 v2(41.899,32.294) 41.899,33.386 42.274,33.76 42.567,33.76 v2(42.607,33.8) ; v2(38.764,46.451) 38.797,46.484 39.189,46.484 C906.2@39.199,46.494 ; v2(38.945,35.739) 39.001,35.739 39.091,35.65 C901.2@39.425,35.65 ; v2(39.522,44.803) 39.578,44.803 39.794,44.587 39.988,44.587 40.15,44.425 ; C901.2@39.525,35.55 C901.2@39.425,35.65 ; C621.2@39.825,25.925 39.835,25.915 39.835,25.521 39.875,25.481 v2(39.875,25.425) 39.875,25.401 40.016,25.26 40.34,25.26 C660.2@40.35,25.25 ; v1(40.175,28.743) C638.2@40.175,29.225 ; C638.2@40.188,29.212 R637.1@40.712,29.212 ; R637.1@40.71,29.225 40.718,29.218 40.725,29.21 R637.1@40.725,29.2 ; X900.4@40.975,46.731 40.987,46.743 40.987,47.487 v2(41,47.5) ; v2(41.275,35.325) 41.29,35.34 41.29,35.715 C927.2@41.3,35.725 ; C641.2@41.825,29.225 41.825,29.222 41.835,29.212 42.365,29.212 42.375,29.202 R640.1@42.375,29.2 42.385,29.19 42.385,28.88 42.275,28.77 v2(42.275,28.725) ; v1(42.159,27.289) 42.212,27.289 42.426,27.075 42.5,27.075 42.65,26.925 42.75,26.925 U606.2@42.8,26.875 ; C921.2@42.375,34.5 42.567,34.308 42.567,33.858 v2@42.616,33.809 ; X900.2@42.379,45.715 42.433,45.715 42.648,45.5 42.648,45.063 42.686,45.025 v1(42.686,45.021) ; v2(42.889,35.508) 42.922,35.508 42.94,35.526 C926.2@42.94,35.925 ; v2(43.475,28.55) C635.2@43.475,29.225 43.475,29.222 43.485,29.212 44.015,29.212 44.025,29.202 R634.1@44.025,29.2 ; R931.2@43.484,47.121 43.484,47.131 43.835,47.482 43.835,47.585 v2(43.875,47.625) 43.931,47.625 44.014,47.708 44.303,47.708 R930.2@44.313,47.718 ; v1(44.136,44.73) 44.157,44.75 44.157,45.368 44.167,45.378 C910.2@44.177,45.378 ; C674.2@44.896,25.632 44.896,25.093 45.275,24.714 v1(45.275,24.659) ; C632.2@45.125,29.225 45.66,29.225 45.685,29.2 45.685,29.033 46.119,28.599 46.26,28.599 v2(46.3,28.559) ; C908.2@45.419,45.9 45.439,45.9 45.449,45.91 45.449,45.972 45.585,46.108 45.585,46.199 45.6,46.213 45.6,46.36 v2(45.642,46.402) ; v2@45.625,46.4 45.975,46.75 U901.3@46.375,46.75 ; v2@45.642,46.4 45.652,46.4 45.802,46.25 U901.4@46.375,46.25 ; U901.2@46.375,47.25 45.875,47.25 v2(45.575,47.55) 45.775,47.75 U901.1@46.375,47.75 ; R674.2@46.625,27.75 46.635,27.75 46.645,27.76 46.645,27.949 46.883,28.187 v2(46.883,28.243) ; v2@46.807,44.121 v2(46.807,44.065) 46.847,44.105 46.847,44.242 47.007,44.402 R850.1@47.007,44.412 ; v2@46.9,28.204 47.021,28.325 C625.2@47.263,28.325 ; C625.2@47.325,28.325 C625.2@47.263,28.325 ; C625.2@47.576,28.638 47.576,28.613 47.326,28.363 47.301,28.363 C625.2@47.263,28.325 ; C804.2@48.02,34.083 48.04,34.083 48.05,34.073 48.05,33.681 48.085,33.646 48.085,33.59 48.165,33.51 48.44,33.51 48.915,33.035 48.915,32.635 C652.2@48.925,32.625 ; C673.2@48.974,26.829 49.581,26.829 49.849,27.097 49.849,27.259 v1(49.887,27.297) ; v2(49.975,31.075) 49.988,31.062 49.988,30.735 49.998,30.725 R688.2@50,30.725 ; C951.2@51.125,47.85 51.145,47.85 51.495,48.2 v1(51.5,48.2) ; v2(51.352,32.336) 51.359,32.343 52.018,32.343 U622.2@52.025,32.35 52.038,32.337 52.89,32.337 C653.2@52.9,32.325 C653.2@52.9,32.325 ; v2(51.675,40.175) 51.731,40.175 51.876,40.03 52.115,40.03 52.125,40.02 C861.2@52.125,40 ; U808.2@52.28,46.2 52.55,46.2 52.75,46.4 C808.2@52.75,47.75 52.747,47.75 52.737,47.76 52.737,48.138 v2(52.725,48.15) ; C655.2@52.5,26.275 52.518,26.293 53.382,26.293 v1(53.4,26.311) ; C860.2@53.075,38 53.444,38 53.494,38.05 v2(53.55,38.05) ; v2(53.125,30.9) Q807.4@53.8,30.9 ; U808.12@53.325,41.155 53.335,41.145 53.335,40.28 53.465,40.15 R852.1@53.475,40.15 ; v2(53.4,36.375) C800.2@53.775,36.75 ; v2(54.967,28.632) 54.967,28.689 55.055,28.777 55.055,29.115 55.075,29.135 55.095,29.135 55.095,29.295 55.1,29.3 Q807.1@55.1,29.9 ; C828.2@56.075,29.775 56.081,29.769 56.081,29.269 v2(56.086,29.264) ; v2(56.775,42.175) 56.815,42.135 57.122,42.135 57.282,41.975 57.302,41.975 57.312,41.965 C865.2@57.312,41.945 ; v2(56.813,39.962) 56.82,39.968 57.318,39.968 C864.2@57.325,39.975 ; R814.1@57.254,36.99 57.254,36.417 57.125,36.288 v2(57.125,36.232) 57.165,36.271 57.165,36.34 57.406,36.581 C867.2@57.78,36.581 ; v2(58.3,33.143) 58.3,33.156 58.345,33.201 58.345,33.615 58.355,33.625 C866.2@58.375,33.625 ; R851.1@58.872,41.832 58.882,41.832 58.892,41.842 58.892,41.852 58.895,41.855 58.895,42.089 59.1,42.294 v2(59.1,42.35) ; R853.1@59.05,35.725 59.06,35.735 59.338,35.735 59.353,35.75 ; v2(59.372,34.922) 59.372,35.015 59.375,35.018 59.375,35.728 59.353,35.75 ; v2(59.475,31.2) 59.531,31.2 59.581,31.25 U810.7@60.125,31.25 ; v2(59.95,45.3) 59.99,45.26 59.99,44.75 U800.7@60.125,44.75 ; v2(60.05,40.85) 60.087,40.812 60.087,40.25 U802.7@60.125,40.25 ; U806.7@60.125,35.75 59.353,35.75 ; v2(63.925,42.85) 63.925,42.906 63.965,42.946 63.965,43.315 C803.2@63.975,43.325 ; C827.2@63.975,29.825 63.984,29.816 63.984,29.384 v2(63.993,29.375) ; C805.2@63.975,38.825 63.984,38.816 63.984,38.363 v2(63.993,38.354) ; LED101.2@67,15.296 67,16.129 67.096,16.225 67.096,16.279 ; C423.2@70.62,8.087 71.274,8.087 v1(71.289,8.073) ; v1(71.388,10.467) 71.426,10.429 71.426,10.281 71.594,10.113 R407.1@71.594,10.103 ; v1(71.825,16.2) 71.837,16.188 71.837,15.608 ; LED100.2@71.85,15.296 71.837,15.308 71.837,15.608 ; 71.85,15.596 71.837,15.608 ; v1(79.525,26.911) 79.525,27.5 C422.2@79.625,27.6 ; C13.2@79.6,32.675 80.061,32.675 v1(80.1,32.713) ; C9.2@79.6,35.175 79.976,35.175 v1(80.1,35.299) ; C421.2@79.625,30.775 v1@79.625,31.326 ; v1@79.627,31.327 v1(79.627,31.489) ; v1(82.799,31.549) U1.G3@83.2,31.95 ; R105.2@83.574,7.92 83.241,8.253 83.241,8.788 83.254,8.8 83.266,8.812 83.717,8.812 83.727,8.822 C103.2@83.727,8.824 ; v1(83.599,34.751) U1.D4@84,34.35 ; C40.2@83.925,24.767 83.941,24.784 84.459,24.784 v1(84.475,24.8) ; U1.K4@84,29.55 v1(84.401,29.149) ; U1.D4@84,34.35 v1(84.4,33.95) ; C14.2@84.125,27.1 v1@84.125,27.475 ; U1.H6@85.6,31.15 v1(86.001,30.749) ; v1(86.112,50.862) 86.174,50.8 86.2,50.8 86.225,50.825 86.225,51.475 D809.2@86.25,51.5 ; v1(86.2,26.5) 86.225,26.525 X1.2@87.025,26.525 ; U1.L7@86.4,28.75 v1(86.801,28.349) ; U1.K7@86.4,29.55 v1(86.801,29.149) ; U1.C7@86.4,35.15 v1(86.801,35.551) ; U1.G9@88,31.95 v1(88.401,31.549) ; U1.F9@88,32.75 v1(88.401,33.151) ; U1.K10@88.8,29.55 v1(89.201,29.149) ; v1(88.9,24.5) 88.15,24.5 88.05,24.4 88.05,25.05 X1.4@88.425,25.425 89.2,25.425 C418.2@89.6,25.825 ; LED900.2@89.25,56.45 89.258,56.458 89.938,56.458 v1(89.946,56.466) ; v1(90.8,28.4) 90.825,28.375 C5.2@91.4,28.375 ; C4.2@90.875,27.1 90.885,27.11 91.128,27.11 91.282,27.264 v1(91.336,27.264) ; v1(90.91,31.025) 90.949,30.987 91.008,30.987 91.4,30.595 C6.2@91.4,30.575 ; C16.2@91.5,33.1 91.662,32.938 92.112,32.938 92.15,32.9 v1(92.125,32.875) ; C15.2@91.5,34.675 v1(91.5,35.2) ; v1(92.4,33.7) C10.2@92.4,34.5 ; v1(92.639,26.145) 92.677,26.183 92.677,26.777 C3.2@92.8,26.9 ; C401.2@93.1,38 93.13,38.03 93.13,38.744 v1(93.159,38.773) ; C402.2@93.5,36.625 93.5,36.567 93.55,36.517 94.14,36.517 v1(94.178,36.556) ; v1(94.825,56.475) P801.15@94.825,57.841 ; v1(94.925,8.209) 94.979,8.209 95.082,8.106 95.457,8.106 R104.2@95.607,7.956 ; v1(95.4,10.975) 95.454,10.975 95.576,10.853 95.759,10.853 95.769,10.843 C102.2@95.769,10.823 ; P801.13@96.095,57.841 96.097,57.839 96.097,56.453 v1(96.1,56.45) ; v1(97.2,51.35) D806.2@97.2,52 ; P801.11@97.365,57.841 97.383,57.824 97.383,56.493 v1(97.4,56.475) ; C200.2@98.2,21.7 v1(100.3,21.7) ; P801.9@98.635,57.841 98.643,57.834 98.643,56.483 v1(98.65,56.475) ; v1(98.7,51.325) D807.2@98.7,52 ; v1(99.9,56.45) 99.903,56.452 99.903,57.839 P801.7@99.905,57.841 ; D808.2@103.75,52 103.751,51.999 103.751,51.202 v1(103.752,51.201) ; v1(105.972,9.575) 105.972,9.521 106.12,9.373 106.12,9.136 106.13,9.126 C199.2@106.15,9.126
  Top Layer w0.305: v1(20.854,2.174) 20.864,2.164 20.864,1.508 20.872,1.5 C706.2@20.875,1.5 ; v1(78.65,9.476) 78.675,9.451 78.675,8.875 D400.2@78.7,8.85 ; v1@80.3,2.86 P400.5@80.3,4.85 80.323,4.872 80.323,5.822 80.483,5.982 v1(80.483,6.035) ; v1(94.925,8.209) v1@94.929,8.205 ; v1(97.058,34.988) 97.111,34.988 97.251,35.128 97.573,35.128 97.581,35.136 C8.2@97.581,35.156 ; v1(99.212,40.853) 99.287,40.778 R7.1@99.287,40.162
  Top Layer w0.5: C611.2@24.562,42.155 24.562,42.13 24.712,41.98 25.358,41.98 v1(25.38,41.958) ; C607.2@25.412,45.18 25.456,45.225 v1(26.275,45.225) ; C714.2@27.875,34.95 v2(27.875,35.725) ; C609.2@37.35,29.025 37.573,28.802 37.573,28.552 v2(37.575,28.55) ; v2@37.648,28.55 37.845,28.353 37.845,28.28 R628.2@38.125,28 ; v1(71.289,8.073) 72.09,8.073 U400.7@72.387,7.776 72.472,7.86 74.067,7.86 C420.2@74.151,7.945 74.126,7.945 73.976,8.095 73.976,8.5 v1(73.782,8.694)
  Top Layer w0.508: v1(74.661,56.27) 74.661,57.997 P800.19@74.666,58.002 ; P800.17@75.936,58.002 75.961,57.977 v1(75.961,56.27) ; P800.15@77.206,58.002 77.211,57.997 v1(77.211,56.27) ; P800.5@83.556,58.002 83.561,57.997 v1(83.561,56.32) ; v1(84.811,56.32) 84.811,57.987 P800.3@84.826,58.002
  Top Layer w0.635: v1@81.016,56.275 P800.9@81.016,58.002
  Bottom Layer w0.3: TPJ913.1@50.75,30.5 52.669,30.5 53.069,30.9 v2(53.125,30.9) ; v1(80.045,21.909) 80.057,21.897 80.523,21.897 81.218,22.592 R240.1@81.218,22.617 ; v1(80.354,14.546) 80.408,14.546 80.487,14.625 R244.1@81.263,14.625 ; v1(90.8,28.4) v1@90.838,28.438 ; v1(90.882,37.998) v1@90.92,37.96
  Bottom Layer w0.508: P601.28@6.2,48.475 6.2,48.611 P601.28@6.52,48.931 ; TPJ614.1@7.548,49.799 7.642,49.894 8.755,49.894 v1(8.766,49.905)
  other v1: 13.77,0.909 105.957,1.332 109.791,1.332 101.403,1.422 87.584,1.449 0.965,1.517 23.895,2.358 80.291,2.85 107.649,3.843 83.35,4.693 0.945,4.716 21.8,4.7 26,4.8 103.7,4.8 13.608,5.139 92.844,5.31 23.868,5.373 77.879,6.308 99.864,6.867 28.233,7.11 32.13,7.155 34.947,7.326 15.435,7.389 42.066,7.605 103.698,7.614 39.357,7.695 47.097,7.722 44.604,7.749 90.035,8.108 91.079,8.27 98.01,8.973 83.254,9.039 105.39,10.368 22.743,10.764 61.902,11.322 76.562,11.537 91.3,11.6 103.491,11.763 97.974,12.015 85.833,12.042 20.221,12.363 28.152,12.357 77.706,12.852 85.743,13.428 70.862,13.584 114.117,13.707 94.257,13.797 61.929,14.049 20.158,14.23 88.947,14.346 100.1,14.4 105.1,14.5 91.17,15.12 90.063,15.174 66.324,15.42 22.104,15.534 103.473,15.966 5.775,16 7,16 8,16 62.4,16.1 88.992,16.272 64.45,16.525 20.124,16.623 28.152,16.695 91.17,16.767 5.775,17 7,17 8,17 73.952,17.045 72.161,17.279 114.117,17.388 21.852,17.415 92.519,17.414 107.557,17.57 109.557,17.57 63.4,17.6 111.422,17.6 5.775,18 7,18 8,18 20.124,18.495 77.759,19.304 107.557,19.57 110.95,19.57 27.756,20 31.3,20.4 64.246,20.471 94.761,20.601 20.412,20.682 42.615,20.691 36.7,20.7 44.73,20.709 40.635,20.727 87.876,21.576 91.124,21.576 74.6,21.6 22.473,22.05 39.195,22.176 111.321,22.779 114.147,22.77 71.124,23.091 68.129,23.111 59.7,23.836 66.7,24 72.263,24.088 27.522,24.3 29.808,24.3 90.053,24.56 20.358,24.66 71.028,25.056 24.75,25.119 111.33,25.245 114.174,25.299 85.422,25.497 72.306,25.815 76.7,26 93.708,26.19 27.45,26.298 71.101,26.868 17.613,27.27 94.302,27.378 72.263,27.511 13.599,27.549 84,27.6 15.984,27.792 111.465,27.972 114.138,27.972 13.446,28.791 29.286,28.98 31.185,28.998 100.544,29.684 85.2,29.949 15.867,29.97 23.211,30.118 114.129,30.447 111.51,30.492 99.288,31.014 12.771,31.275 72.279,31.806 102.564,32.139 111.591,32.859 85.599,33.048 114.183,33.12 23.031,33.372 15.693,33.402 18.927,33.489 12.735,33.516 0.846,33.669 71.982,34.335 74.718,35.046 112.653,35.316 92.457,35.37 51.381,35.451 97.075,35.675 102.445,35.887 0.846,36.693 99.015,36.692 114.12,36.711 15.678,36.783 18.972,36.927 12.6,37.251 29.075,37.45 30.322,37.549 33.504,37.555 98.019,37.548 27.954,37.737 35.703,37.782 24.425,37.925 21.213,38.196 74.95,38.225 18.954,38.52 97.837,38.54 30.123,38.727 31.881,38.708 31,38.825 28.95,38.875 23.472,38.916 35.887,38.919 32.8,38.95 25.2,38.979 0.846,39.222 28.134,39.303 33.507,40.023 23.661,40.329 12.609,40.455 18.954,40.626 15.331,41.388 18.945,41.553 74.187,41.589 83.376,41.634 0.846,41.751 30.42,41.94 114.084,43.002 97.983,43.119 33.444,43.245 9.396,43.488 12.744,43.632 5.049,43.839 0.846,43.902 15.395,43.923 91.665,44.307 74.115,44.325 82.998,44.325 85.284,44.343 79.596,44.361 22.925,44.6 23.85,44.6 95.148,45.018 22.925,45.225 23.85,45.225 34.011,45.333 104.841,46.008 112.554,46.125 32.427,46.521 35.793,46.521 1.847,46.746 10.287,46.746 92.034,46.755 0.818,46.761 3,46.79 14.58,46.8 101.286,46.8 16.695,46.818 19.017,46.818 12.627,46.881 6.59,46.889 7.922,46.889 8.978,46.89 4.124,46.916 5.355,46.917 60.088,47.617 21.368,47.622 82.971,47.628 19.197,47.988 11.727,48.042 13.671,48.087 15.39,48.096 17.1,48.087 9.481,48.147 114.138,48.339 10.575,49.077 79.641,49.221 12.6,49.248 94.05,49.401 27.396,49.446 112.5,49.5 20.025,49.725 91.953,50.031 9.411,50.082 16.825,50.1 11.655,50.301 80.955,50.31 103.68,50.328 114.138,50.616 30.834,51.21 15.025,51.6 107.982,51.615 109.359,51.957 34.974,52.029 19.593,52.461 114.12,52.56 12.294,52.659 112.6,53 22.671,53.019 64.893,53.169 16.2,53.275 67.894,53.413 14.15,53.55 90.54,54.288 47.4,55.9 16.623,56.007 19.359,56.007 22.869,56.079 26.784,56.187 88.191,56.277 108.468,56.376 9.466,56.734 3.852,58.077 4.923,58.086 8.506,58.078 6.03,58.149 7.353,58.194 1.137,58.313 2.485,58.313 109,58.3 106.416,58.689 1.314,59.049 29.637,59.031 8.568,59.085 12.204,59.094 20.016,59.094 87.111,59.085 91.233,59.085 15.768,59.103 89.307,59.103 22.689,59.13 26.523,59.13
  other v2: 33.5,27.575 34.45,27.575 21.075,28 33.5,28.225 34.4,28.225 48.124,33.551 31.25,35.475 31.25,36.35 44.35,41.775 54.075,43.9
HFXTAL_N: C418.1 U1.L9 X1.1 | length 3.7
  Top Layer w0.1: U1.L9@88,28.752 88,26.9 88.064,26.836 88.375,26.525 X1.1@88.425,26.525 89.45,26.525 C418.1@89.6,26.375
HFXTAL_P: C417.1 U1.L8 X1.3 | length 5
  Top Layer w0.1: U1.L8@87.2,28.752 87.7,28.251 87.7,26.1 X1.3@87.025,25.425 87.025,24.725 87.325,24.425 C417.1@87.325,24.4
LCD_BCAP_N: C500.2 J101.7 U1.K3 | length 70.6
  Top Layer w0.1: v1(82.554,26.451) 82.75,26.647 82.75,27.175 82.656,27.269 82.656,28.338 82.75,28.432 82.75,29.102 U1.K3@83.2,29.55 U1.K3@83.2,29.55
  Signal Layer 3 w0.1: J101.7@38.57,3.262 40.732,1.1 70.4,1.1 72.4,3.1 72.4,5.1 73.564,6.264 75.163,6.264 76.149,7.25 79.883,7.25 v1(80.344,6.789)
  Signal Layer 4 w0.1: v1@80.3,6.833 80.3,11.3 82.554,13.554 82.554,25.046 82.536,25.064 82.536,25.386 82.554,25.404 v1(82.554,26.451)
LCD_BCAP_P: C500.1 J101.5 U1.J4 | length 77
  Top Layer w0.1: v1(83.35,26.4) 83.3,26.45 83.3,27.175 83.601,27.476 83.601,29.95 U1.J4@84,30.35
  Signal Layer 3 w0.1: J101.5@36.03,3.262 38.692,0.6 70.8,0.6 73.744,3.544 82.119,3.544 82.616,4.04 v1(82.616,5.73)
  Signal Layer 4 w0.1: v1(82.616,5.73) 81.97,6.376 81.97,10.869 83.9,12.8 83.9,25.85 v1(83.35,26.4)
LCD_BEXT: C40.1 J101.9 U1.L3 | length 65.9
  Top Layer w0.1: C40.1@82.925,24.767 v1(82.925,25.225) v1@82.925,25.275 ; v1(83.05,28.175) 83.2,28.325 U1.L3@83.2,28.75
  Signal Layer 3 w0.1: J101.9@41.11,3.262 42.772,1.6 70.069,1.6 71.6,3.131 71.6,5.083 73.006,6.489 75.019,6.489 77.488,8.958 v1(80.908,8.958)
  Signal Layer 4 w0.1: v1@80.872,8.994 80.872,10.773 83.2,13.1 83.2,24.934 v1@82.984,25.15 ; v1@82.956,25.356 82.956,27 83.05,27.094 v1(83.05,28.175)
LCD_COM0: LCD1.21 U1.A9 | length 60.4
  Top Layer w0.1: v1(87.822,37.242) 87.822,36.928 U1.A9@88,36.75
  Signal Layer 4 w0.1: LCD1.21@46.5,49.2 48.413,51.113 69.788,51.113 73.1,54.425 85.35,54.425 88.414,51.361 88.414,44.639 87.711,43.936 87.711,37.461 87.822,37.35 v1(87.822,37.242)
LCD_COM1: LCD1.22 U1.B9 | length 64.8
  Top Layer w0.1: v1(87.601,35.55) U1.B9@88,35.949
  Signal Layer 4 w0.1: LCD1.22@44.5,49.2 46.645,51.345 69.642,51.345 72.972,54.675 85.383,54.675 88.614,51.444 88.614,44.464 87.911,43.761 87.911,37.703 88.211,37.403 88.211,36.389 87.812,35.99 87.812,35.944 87.601,35.733 v1(87.601,35.55)
LCD_COM2: LCD1.23 U1.C9 | length 67
  Top Layer w0.1: U1.C9@88.001,35.15 v1(88.401,35.55)
  Signal Layer 4 w0.1: LCD1.23@42.5,49.2 44.861,51.561 69.534,51.561 72.898,54.925 85.725,54.925 88.814,51.836 88.814,40.014 v1(88.8,40) 88.8,36.413 88.401,36.013 v1(88.401,35.55)
LCD_COM3: LCD1.24 U1.D9 | length 71.5
  Top Layer w0.1: U1.D9@88,34.35 v1(88.401,34.75)
  Signal Layer 4 w0.1: LCD1.24@40.5,49.2 43.095,51.795 69.413,51.795 72.907,55.288 86.437,55.288 89.725,52 89.725,46.5 89.275,46.05 89.275,36.425 88.795,35.945 88.795,35.143 v1(88.401,34.75)
LCD_COM4: LCD1.25 U1.F3 | length 60.5
  Top Layer w0.1: v1(82.8,33.149) U1.F3@83.2,32.75
  Signal Layer 3 w0.1: LCD1.25@38.5,49.2 39.893,50.593 70.007,50.593 72.687,47.913 81.087,47.913 v1(81.1,47.9)
  Signal Layer 4 w0.1: v1(81.1,47.9) 81.1,39.964 80.922,39.786 80.922,38.065 81.589,37.399 81.589,34.228 82.668,33.149 v1(82.8,33.149)
LCD_COM5: LCD1.26 U1.F4 | length 67.3
  Top Layer w0.1: v1(84.4,33.149) 84.04,32.79 v1(84.4,33.149)
  Signal Layer 3 w0.1: LCD1.26@36.5,49.2 38.175,50.875 70.2,50.875 72.685,48.39 84.404,48.39 84.503,48.489 v1(84.611,48.489)
  Signal Layer 4 w0.1: v1(84.4,33.149) 84.4,33.268 84.8,33.667 84.8,36.95 85.3,37.45 85.3,37.454 85.785,37.939 85.785,38.565 84.865,39.485 84.865,47.66 84.611,47.914 v1(84.611,48.489)
LCD_COM6: LCD1.27 U1.G1 | length 64.4
  Top Layer w0.1: v1(81.2,31.549) U1.G1@81.558,31.907 ; U1.G1@81.6,31.95 U1.G1@81.558,31.907 ; U1.G1@81.601,31.949 81.557,31.905 U1.G1@81.558,31.907
  Signal Layer 3 w0.1: LCD1.27@34.5,49.2 36.475,51.175 70.4,51.175 72.851,48.724 76.859,48.724 76.981,48.845 v1(77.624,48.845)
  Signal Layer 4 w0.1: v1(77.624,48.845) 78.189,48.28 78.189,39.936 80.103,38.022 80.103,36.756 80.725,36.134 80.725,34.101 81.2,33.627 v1(81.2,31.549)
LCD_COM7: LCD1.28 U1.G2 | length 67.6
  Top Layer w0.1: v1(82,31.549) U1.G2@82.4,31.95
  Signal Layer 3 w0.1: LCD1.28@32.5,49.2 34.775,51.475 70.55,51.475 73.101,48.924 76.776,48.924 77.253,49.4 v1(77.35,49.4)
  Signal Layer 4 w0.1: v1(77.35,49.4) 77.77,49.4 78.389,48.781 78.389,40.286 80.306,38.369 80.306,36.836 80.925,36.217 80.925,34.184 81.403,33.706 81.403,32.146 v1(82,31.549)
LCD_SEG12: LCD1.1 U1.B1 | length 82.4
  Top Layer w0.1: v1(79.5,37) 80.55,37 U1.B1@81.6,35.95 ; U1.B1@81.6,35.95 81.602,35.95 U1.B1@81.6,35.95
  Signal Layer 4 w0.1: LCD1.1@32.5,23.8 37.3,19 61.2,19 62.225,17.975 62.225,16.875 66.208,12.892 68.658,12.892 69.353,12.197 75.399,12.197 77.125,13.924 77.125,21.792 ; v1(79.5,37) 79.5,36.657 79.894,36.263 79.894,35.65 79.706,35.463 79.706,32.094 80.15,31.65 80.15,24.817 ; 77.125,21.792 80.15,24.817 ; 77.125,21.792 80.15,24.817
LCD_SEG13: LCD1.2 U1.C2 | length 60
  Top Layer w0.1: v1(82,35.55) U1.C2@82.4,35.15
  Signal Layer 3 w0.1: LCD1.2@34.5,23.8 34.5,22.625 35.75,21.375 59.975,21.375 60.4,21.8 72.8,21.8 v1(75.8,24.8) ; v1(76.3,32.7) 76.571,32.971 78.986,32.971 80.005,33.989 80.439,33.989 v1(82,35.55)
  Signal Layer 4 w0.1: v1(75.8,24.8) 75.8,26.264 75.998,26.462 75.998,32.398 v1(76.3,32.7)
